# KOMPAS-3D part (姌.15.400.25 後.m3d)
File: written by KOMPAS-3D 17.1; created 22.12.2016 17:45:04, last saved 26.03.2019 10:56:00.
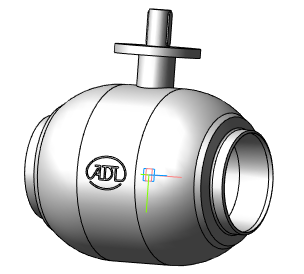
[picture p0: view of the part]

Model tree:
1. Операция без истории:3  (labels: Сталь 20  ГОСТ 1050-88)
